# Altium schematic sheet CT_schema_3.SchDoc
size 316 x 200 mm
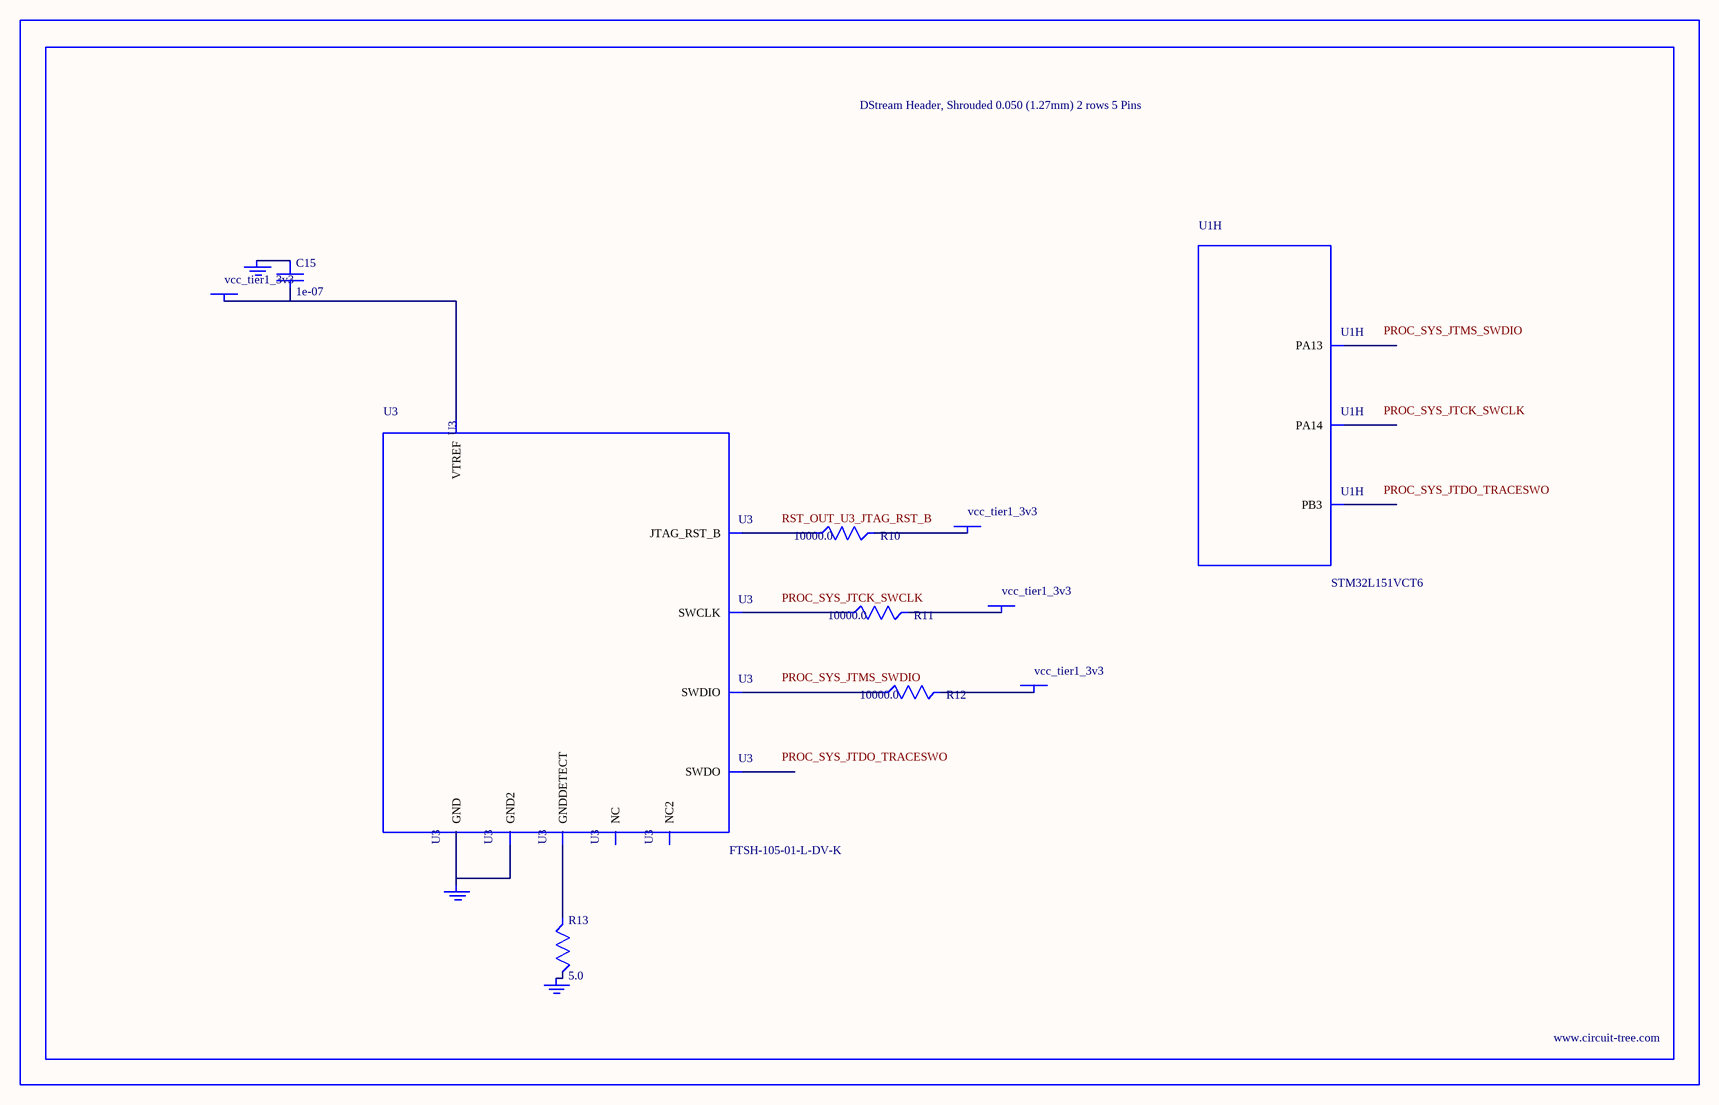
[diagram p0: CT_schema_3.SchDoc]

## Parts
BORDER2  (no value)
C15  1e-07  [C0402]
GND_INSTANCE_2_0  (no value)
GND_INSTANCE_2_1  (no value)
GND_INSTANCE_2_2  (no value)
POWER_INSTANCE_2_0  vcc_tier1_3v3
POWER_INSTANCE_2_1  vcc_tier1_3v3
POWER_INSTANCE_2_2  vcc_tier1_3v3
POWER_INSTANCE_2_3  vcc_tier1_3v3
R10  10000.0  [R0603]
R11  10000.0  [R0603]
R12  10000.0  [R0603]
R13  5.0  [R0603]
U1  STM32L151VCT6  [LQFP100]  (part H of 11)
U3  FTSH-105-01-L-DV-K  [SAMTEC_FTSH-105-01-L-DV-K]

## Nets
NetC15_1: C15.1 GND_INSTANCE_2_0.0(GND)
NetC15_2: C15.2 POWER_INSTANCE_2_0.0(PWR) U3.1(VTREF)
NetGND_INSTANCE_2_1_0: GND_INSTANCE_2_1.0(GND) R13.2
NetGND_INSTANCE_2_2_0: GND_INSTANCE_2_2.0(GND) U3.3(GND) U3.5(GND2)
NetPOWER_INSTANCE_2_1_0: POWER_INSTANCE_2_1.0(PWR) R12.2
NetPOWER_INSTANCE_2_2_0: POWER_INSTANCE_2_2.0(PWR) R11.2
NetPOWER_INSTANCE_2_3_0: POWER_INSTANCE_2_3.0(PWR) R10.2
NetR10_1: R10.1 U3.10(JTAG_RST_B)
NetR11_1: R11.1 U3.4(SWCLK)
NetR12_1: R12.1 U3.2(SWDIO)
NetR13_1: R13.1 U3.9(GNDDETECT)

Not connected (* = marked no-connect by the designer): U1 72(PA13) 76(PA14) 89(PB3); U3 6(SWDO) 7(NC) 8(NC2)

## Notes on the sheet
- Labels drawn without touching a wire or pin: PROC_SYS_JTCK_SWCLK, PROC_SYS_JTDO_TRACESWO, PROC_SYS_JTMS_SWDIO, RST_OUT_U3_JTAG_RST_B

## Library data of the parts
BORDER2 = BORDER_PAGE2
C15 = C0402C104K3RACTU
GND_INSTANCE_2_0-GND_INSTANCE_2_2 = GND
POWER_INSTANCE_2_0-POWER_INSTANCE_2_3 = PWR
R10-R12 = RC0603JR-0710KL
R13 = ERJ-3GEYJ5R1V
